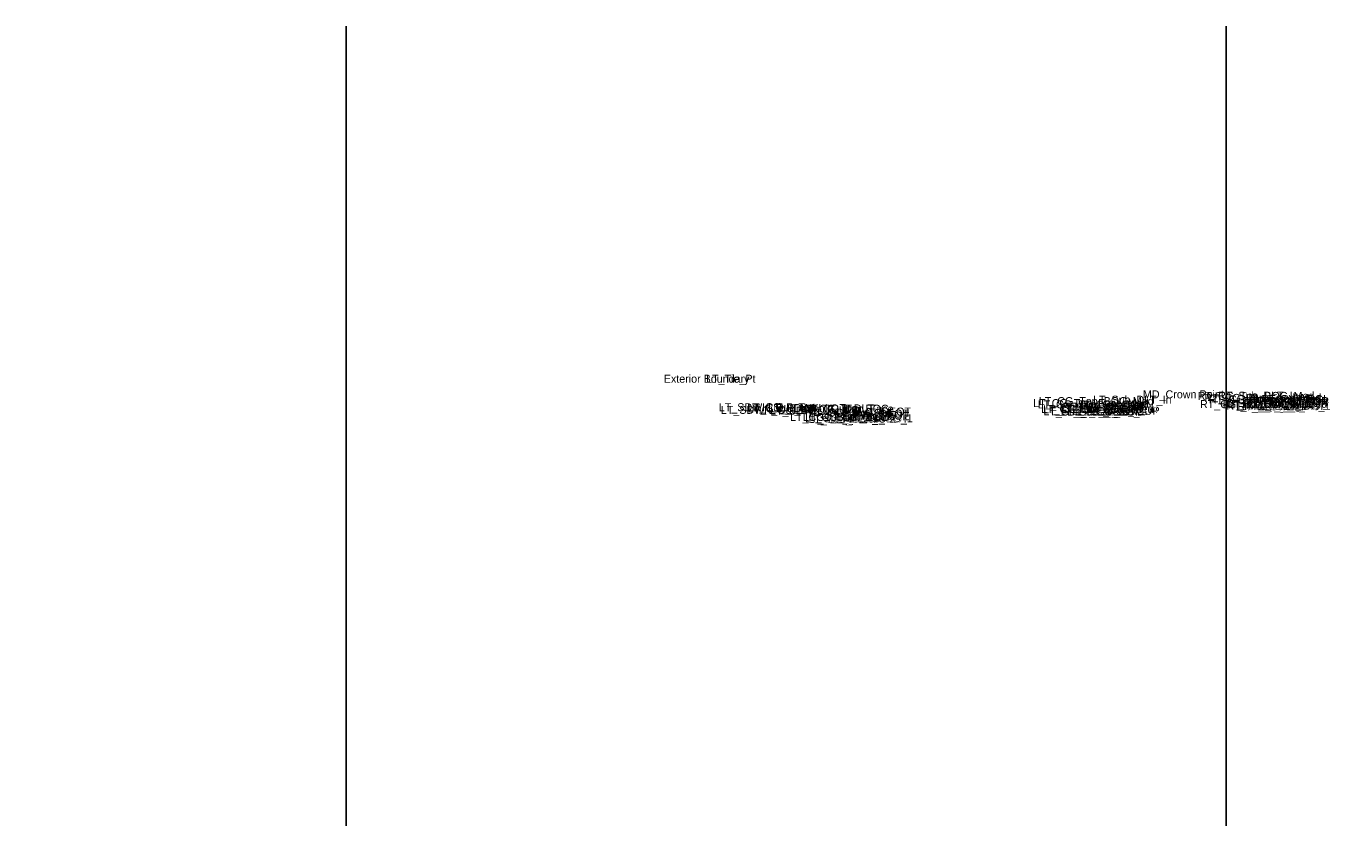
# Model space of a CAD drawing. Extents: x 0 to 6300, y -50 to 9550.
# Drawn here: x 3000 to 3162.9, y -50 to 50 of the extents above; entities that cross this region are included whole.
import ezdxf

# ---------------------------------------------------------------- set-up
doc = ezdxf.new("R2010")
doc.units = 0
for name, color, linetype in [('Default', 7, 'Continuous'), ('Prop XS Exc Vertical Line 1', 7, 'Continuous'), ('Prop XS Exc Vertical Line 2', 7, 'Continuous')]:
    doc.layers.add(name, color=color, linetype=linetype)

msp = doc.modelspace()

# ---------------------------------------------------------------- linework, layer by layer
at = {"layer": 'Prop XS Exc Vertical Line 1'}
msp.add_line((3040, 50), (3040, -50), dxfattribs=at)
at = {"layer": 'Prop XS Exc Vertical Line 2'}
msp.add_line((3150, 50), (3150, -50), dxfattribs=at)

# ---------------------------------------------------------------- texts
at = {"layer": 'Default'}
for s, height, p in [('Exterior Boundary', 1, (3079.7, 5.41)), ('LT_Tie_Pt', 1, (3084.99, 5.41)), ('LT_CG_Top_Face_Med', 1, (3125.87, 2.36)), ('LT_CG_Top_BOC_Med', 1, (3126.57, 2.61)), ('LT_Sub_DLT_In', 1, (3133.34, 2.79)), ('MD_Crown Point', 1, (3139.58, 3.46)), ('RT_CG_Top_BOC_Med', 1, (3146.43, 3.26)), ('RT_CG_Bot_BOC_Med', 1, (3146.71, 2.23)), ('RT_CG_Top_Face_Med', 1, (3147.25, 3.01)), ('RT_CG_Top_Gut_Med', 1, (3147.8, 2.84)), ('RT_Sub_DLT_In', 1, (3148.98, 3.3)), ('RT_CG1_Shelf_In', 1, (3149.57, 2.22)), ('RT_CG_Bot_IE_Med', 1, (3149.98, 2.28)), ('RT_PV2_OEEOP', 1, (3152.17, 2.61)), ('RT_PV3_OEEOP', 1, (3152.17, 2.36)), ('RT_PV2_IEEOP', 1, (3152.93, 2.61)), ('RT_PV2_PGL', 1, (3154.15, 2.61)), ('RT_PV1_PGL', 1, (3154.38, 2.86)), ('LT_SDWK_Out_Top', 1, (3086.58, 1.85)), ('LT_SDWK_Out_Bot', 1, (3086.83, 1.52)), ('LT_CSLP_Pnt', 1, (3090.1, 1.85)), ('LT_Sub_Trench_Out_DLT', 1, (3090.21, 1.7)), ('LT_SDWK_In_Top', 1, (3092.74, 1.75)), ('LT_SDWK_In_Bot', 1, (3092.99, 1.42)), ('LT_CG1_Shelf_Out', 1, (3095.48, 0.63)), ('LT_CG_Top_BOC', 1, (3096.81, 1.66)), ('LT_CG_Bot_BOC', 1, (3097.09, 0.64)), ('LT_CG_Top_Face', 1, (3097.34, 1.66)), ('LT_CG_Top_Gut', 1, (3097.87, 1.16)), ('LT_PV2_OEOT', 1, (3100.99, 1.05)), ('LT_PV3_OEOT', 1, (3100.99, 0.8)), ('LT_PV1_OEOT', 1, (3101.23, 1.3)), ('LT_CG_Bot_IE', 1, (3101.34, 0.72)), ('LT_CG_Top_Gut_Med', 1, (3126.42, 2.2)), ('LT_CG_Bot_BOC_Med', 1, (3126.85, 1.64)), ('LT_CG_Bot_IE_Med', 1, (3127.09, 1.59)), ('LT_Sub_IEOT_CG_1', 1, (3127.13, 1.34)), ('LT_PV2_OEEOP', 1, (3129.29, 1.92)), ('LT_PV3_OEEOP', 1, (3129.29, 1.67)), ('LT_Sub_OEEOP', 1, (3129.33, 1.3)), ('LT_PV2_IEEOP', 1, (3130.05, 1.92)), ('LT_Sub_IEEOP', 1, (3130.09, 1.3)), ('LT_CG1_Shelf_In', 1, (3130.71, 1.65)), ('LT_PV2_PGL', 1, (3131.26, 1.92)), ('LT_Sub_PGL', 1, (3131.31, 1.3)), ('LT_PV1_PGL', 1, (3131.5, 2.17)), ('LT_Sub_IEOP', 1, (3133.04, 1.41)), ('RT_Sub_IEOT_CG_1', 1, (3150.01, 2.03)), ('RT_Sub_IEOP', 1, (3151.4, 1.96)), ('RT_Sub_OEEOP', 1, (3152.21, 1.99)), ('RT_Sub_IEEOP', 1, (3152.97, 1.99)), ('RT_Sub_PGL', 1, (3154.19, 1.99)), ('-', 0.0001, (3000, 0)), ('LT_Sub_OEOT_CG_1', 1, (3097.36, 0.47)), ('LT_Sub_OEOP', 1, (3097.77, 0.37)), ('LT_Sub_OEOT', 1, (3101.04, 0.43))]:
    msp.add_text(s, height=height, dxfattribs=at).set_placement(p)

doc.saveas('drawing.dxf')
